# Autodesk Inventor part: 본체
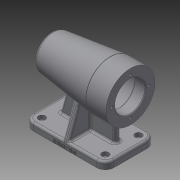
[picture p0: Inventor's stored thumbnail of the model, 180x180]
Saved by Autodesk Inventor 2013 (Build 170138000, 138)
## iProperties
Created: 2018-09
Part Number: 본체
Material: 일반
Document SubType Name: Modeling
Designer: Administrator
Density: 1 g/cm^3
Author: Administrator
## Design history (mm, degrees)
sketch "스케치1"
  geometry: L1 (0, 0)-(0, 34); L2 (0, 34)-(-28, 34); L3 (-28, 34)-(-108.27, 24.144); L4 (-112, 0)-(0, 0); A1 r 80 centre (-32, 0) between (-108.27, 24.144) and (-112, 0); 1 further point
  constraints: 8 end point, 2 point on circle, 1 centre point, 1 coincident, 1 horizontal alignment, 1 perpendicular, 1 vertical
  dimensions: "d0" = 68 diameter of L2 L4; "d3" = 28 distance of L1.end L2.end; "d4" = 7 deg angle of L2 L3; "d5" = 160 diameter of A1; "d6" = 112 distance from line of L1 L4.start
revolve "회전1" sketch "스케치1" stored, may be unused: angle "d7" = 90 deg
hole "구멍1" diameter "d10" = 42; stored, may be unused: countersink angle "d14" = 90 deg, drill point angle "d16" = 0 deg; dims "d11" = 6, "d12" = 4, "d13" = 2, "d15" = 15, "d17" = 10, "d18" = 10
sketch "스케치2"
  geometry: C1 r 21 at (0, 0) reference; C2 r 24 at (0, 0)
  constraints: 1 centre point, 1 coincident
  dimensions: "d19" = 48 diameter of C2
extrude "돌출1" cut sketch "스케치2" distance "d21" = 54; taper "d22" = 0 deg
hole "구멍2" diameter "d25" = 42; stored, may be unused: countersink angle "d29" = 90 deg, drill point angle "d31" = 0 deg; dims "d26" = 6, "d27" = 4, "d28" = 2, "d30" = 12, "d32" = 10, "d33" = 10
hole "구멍3" diameter "d36" = 35; stored, may be unused: countersink angle "d40" = 90 deg, drill point angle "d42" = 0 deg; dims "d37" = 6, "d38" = 4, "d39" = 2, "d41" = 18, "d43" = 10, "d44" = 10
hole "구멍4" diameter "d47" = 32; stored, may be unused: countersink angle "d51" = 90 deg, drill point angle "d53" = 0 deg; dims "d48" = 6, "d49" = 4, "d50" = 2, "d52" = 4, "d54" = 10, "d55" = 10
hole "구멍5" diameter "d58" = 21; stored, may be unused: countersink angle "d62" = 90 deg, drill point angle "d64" = 0 deg; dims "d56" = 10, "d57" = 10, "d59" = 6, "d60" = 4, "d61" = 2, "d63" = 3
fillet "모깎기1" dims "d65" = 3
fillet "모깎기2" dims "d66" = 0.3
chamfer "모따기1" distance "d67" = 1; stored, may be unused: second distance "d68" = 2, angle "d69" = 45 deg
sketch "스케치3"
  geometry: C1 r 34 at (0, 0) reference; 1 further point
  constraints: 1 vertical alignment
  dimensions: "d70" = 26 distance of C1.centre point (0, 26)
hole "구멍6" sketch "스케치3" at (0, 26) diameter "d71" = 3.242; stored, may be unused: countersink angle "d75" = 90 deg, drill point angle "d77" = 118 deg; dims "d72" = 8, "d73" = 4, "d74" = 2, "d76" = 11
node "작업 평면1"
sketch "스케치4"
  geometry: L1 (-112, -35)-(0, -35); L2 (0, -35)-(0, 35); L3 (0, 35)-(-112, 35); L4 (-112, 35)-(-112, -35); 2 further points
  constraints: 8 end point, 2 coincident, 2 parallel, 1 horizontal, 1 midpoint, 1 perpendicular
  dimensions: "d82" = 70 distance of L1.end L2.end; "d84" = 112 distance of L2.end L3.end
extrude "돌출2" join sketch "스케치4" distance "d85" = 10; taper "d86" = 0 deg
fillet "모깎기3" dims "d87" = 12
node "작업 평면2"
node "작업 평면3"
sketch "스케치11"
  geometry: L1 (0, -23)-(0, 23) reference; L2 (-100, 35)-(-12, 35) reference; L3 (-112, -23)-(-112, 23) reference; L4 (0, 23)-(0, -23) reference; L5 (-12, -35)-(-100, -35) reference; L6 (-52, 4)-(-18, 4); L7 (-18, 4)-(-18, -4); L8 (-18, -4)-(-52, -4); L9 (-52, -4)-(-52, 4); A1 r 12 centre (-100, 23) between (-100, 35) and (-112, 23) reference; A2 r 12 centre (-100, -23) between (-112, -23) and (-100, -35) reference; A3 r 12 centre (-12, 23) between (0, 23) and (-12, 35) reference; A4 r 12 centre (-12, -23) between (-12, -35) and (0, -23) reference; 3 further points
  constraints: 8 end point, 2 parallel, 1 horizontal, 1 horizontal alignment, 1 midpoint, 1 perpendicular
  dimensions: "d128" = 18 distance between parallel lines of L1 L7; "d129" = 8 distance of L6.end L7.end
extrude "돌출6" join sketch "스케치11" stored distance "d130" = 8; taper "d131" = 0 deg
sketch "스케치12"
  geometry: A1 r 12 centre (-100, 23) between (-100, 35) and (-112, 23) reference; A2 r 12 centre (-100, -23) between (-112, -23) and (-100, -35) reference; 3 further points
  constraints: 2 coincident
hole "구멍8" sketch "스케치12" at (-100, 23), (-100, -23) diameter "d132" = 5.5; stored, may be unused: countersink angle "d136" = 90 deg, drill point angle "d138" = 118 deg; dims "d133" = 8, "d134" = 9.5, "d135" = 5.4, "d137" = 11
sketch "스케치13"
  geometry: A1 r 12 centre (-12, -23) between (-12, -35) and (0, -23) reference; A2 r 12 centre (-12, 23) between (0, 23) and (-12, 35) reference; 3 further points
  constraints: 2 coincident
hole "구멍9" sketch "스케치13" at (-12, 23), (-12, -23) diameter "d139" = 5.5; stored, may be unused: countersink angle "d143" = 90 deg, drill point angle "d145" = 118 deg; dims "d140" = 8, "d141" = 9.5, "d142" = 5.4, "d144" = 11
sketch "스케치14"
  geometry: L1 (0, 0)-(88, 0) reference; L2 (100, 0)-(100, 10) reference; 3 further points
  constraints: 1 other
  dimensions: "d153" = 3 distance from line of L1 point (44, 3); "d155" = 56 distance from line of L2 point (44, 3)
feature "엠보싱1" sketch "스케치14" dims "d149" = 0.5, "d150" = 0
fillet "모깎기10" dims "d151" = 3
fillet "모깎기11" dims "d152" = 3
fillet "모깎기12" dims "d156" = 3
node "작업 평면4"
sketch "스케치15"
  geometry: L1 (-35, -69.423)-(-35.5, -69.423) reference; L2 (-35.5, -69.423)-(-35.5, -69.092) reference; L3 (-35.5, -69.092)-(-35, -69.092) reference; L4 (-35, -69.092)-(-35, -67) reference; L5 (-32, -64)-(32, -64) reference; L6 (35, -67)-(35, -74) reference; L7 (35, -74)-(-35, -74) reference; L8 (-35, -74)-(-35, -69.423) reference; L9 (-34.819, -65.974)-(-16.98, -16.961); L10 (16.976, -16.951)-(34.819, -65.974); L11 (-35, -69.423)-(-35.5, -69.423) reference; L12 (-35.5, -69.423)-(-35.5, -69.092) reference; L13 (-35.5, -69.092)-(-35, -69.092) reference; L14 (-35, -69.092)-(-35, -67) reference; L15 (-32, -64)-(32, -64) reference; L16 (35, -67)-(35, -74) reference; L17 (35, -74)-(-35, -74) reference; L18 (-35, -74)-(-35, -69.423) reference; L19 (-35, -69.423)-(-35.5, -69.423) reference; L20 (-35.5, -69.423)-(-35.5, -69.092) reference; L21 (-35.5, -69.092)-(-35, -69.092) reference; L22 (-35, -69.092)-(-35, -67) reference; L23 (-32, -64)-(32, -64) reference; L24 (35, -67)-(35, -74) reference; L25 (35, -74)-(-35, -74) reference; L26 (-35, -74)-(-35, -69.423) reference; L27 (-35, -69.423)-(-35.5, -69.423) reference; L28 (-35.5, -69.423)-(-35.5, -69.092) reference; L29 (-35.5, -69.092)-(-35, -69.092) reference; L30 (-35, -69.092)-(-35, -67) reference; L31 (-32, -64)-(32, -64) reference; L32 (35, -67)-(35, -74) reference; L33 (35, -74)-(-35, -74) reference; L34 (-35, -74)-(-35, -69.423) reference; L35 (-35, -69.423)-(-35.5, -69.423) reference; L36 (-35.5, -69.423)-(-35.5, -69.092) reference; L37 (-35.5, -69.092)-(-35, -69.092) reference; L38 (-35, -69.092)-(-35, -67) reference; L39 (-32, -64)-(32, -64) reference; L40 (35, -67)-(35, -74) reference; L41 (35, -74)-(-35, -74) reference; L42 (-35, -74)-(-35, -69.423) reference; L43 (23, -67)-(-23, -67) reference; L44 (-34.819, -65.974)-(34.819, -65.974); C1 r 30.562 at (0, 0) reference; C2 r 30.562 at (0, 0) reference; C3 r 24 at (0, 0) reference; C4 r 24 at (0, 0) reference; C5 r 30.562 at (0, 0) reference; C6 r 24 at (0, 0) reference; C7 r 30.562 at (0, 0) reference; C8 r 24 at (0, 0) reference; C9 r 30.562 at (0, 0) reference; C10 r 24 at (0, 0) reference; A1 r 3 centre (-32, -67) between (-32, -64) and (-35, -67) reference; A2 r 3 centre (32, -67) between (35, -67) and (32, -64) reference; A3 r 3 centre (-32, -67) between (-32, -64) and (-35, -67) reference; A4 r 3 centre (32, -67) between (35, -67) and (32, -64) reference; A5 r 3 centre (-32, -67) between (-32, -64) and (-35, -67) reference; A6 r 3 centre (32, -67) between (35, -67) and (32, -64) reference; A7 r 3 centre (-32, -67) between (-32, -64) and (-35, -67) reference; A8 r 3 centre (32, -67) between (35, -67) and (32, -64) reference; A9 r 3 centre (-32, -67) between (-32, -64) and (-35, -67) reference; A10 r 3 centre (32, -67) between (35, -67) and (32, -64) reference; A11 r 24 centre (0, 0) between (-16.98, -16.961) and (16.98, -16.961); 2 further points
  constraints: 6 end point, 4 point on circle, 2 tangent, 1 centre point, 1 coincident, 1 point on line, 2 other
  dimensions: "d158" = 20 deg angle of L6 L10; "d159" = 20 deg angle of L8 L9
extrude "돌출7" join sketch "스케치15" stored distance "d160" = 8; taper "d161" = 0 deg
sketch "스케치16"
  geometry: L1 (99, -17.2)-(99, -16) reference; L2 (99, -16)-(102.7, -16) reference; L3 (103, -15.7)-(103, -10.5) reference; L4 (106, -7.5)-(106, 7.5) reference; L5 (103, 10.5)-(103, 15.7) reference; L6 (102.7, 16)-(99, 16) reference; L7 (99, 16)-(99, 17.2) reference; L8 (98.7, 17.5)-(81, 17.5) reference; L9 (81, 17.5)-(81, 20.7) reference; L10 (80.7, 21)-(69, 21) reference; L11 (66, 24)-(18, 24) reference; L12 (15, 21)-(1, 21) reference; L13 (1, 21)-(0, 22) reference; L14 (0, 22)-(0, 24.379) reference; L15 (0, 24.379)-(11, 24.379) reference; L16 (11, 24.379)-(11.974, 26) reference; L17 (11.974, 26)-(11, 27.621) reference; L18 (11, 27.621)-(0, 27.621) reference; L19 (0, 27.621)-(0, 34) reference; L20 (0, 34)-(27.817, 34) reference; L21 (28.182, 33.978)-(106.331, 24.382) reference; L22 (106.331, -24.382)-(60, -30.071) reference; L23 (60, -30.071)-(60, -64) reference; L24 (60, -64)-(109, -64) reference; L25 (112, -67)-(112, -74) reference; L26 (112, -74)-(0, -74) reference; L27 (0, -74)-(0, -67) reference; L28 (3, -64)-(18, -64) reference; L29 (18, -64)-(18, -37) reference; L30 (15, -34)-(0, -34) reference; L31 (0, -34)-(0, -27.621) reference; L32 (0, -27.621)-(11, -27.621) reference; L33 (11, -27.621)-(11.974, -26) reference; L34 (11.974, -26)-(11, -24.379) reference; L35 (11, -24.379)-(0, -24.379) reference; L36 (0, -24.379)-(0, -22) reference; L37 (0, -22)-(1, -21) reference; L38 (1, -21)-(15, -21) reference; L39 (18, -24)-(66, -24) reference; L40 (69, -21)-(80.7, -21) reference; L41 (81, -20.7)-(81, -17.5) reference; L42 (81, -17.5)-(98.7, -17.5) reference; L43 (94, -64)-(82.905, -22.595); A1 r 0.3 centre (98.7, -17.2) between (98.7, -17.5) and (99, -17.2) reference; A2 r 0.3 centre (102.7, -15.7) between (102.7, -16) and (103, -15.7) reference; A3 r 3 centre (103, -7.5) between (103, -10.5) and (106, -7.5) reference; A4 r 3 centre (103, 7.5) between (106, 7.5) and (103, 10.5) reference; A5 r 0.3 centre (102.7, 15.7) between (103, 15.7) and (102.7, 16) reference; A6 r 0.3 centre (98.7, 17.2) between (99, 17.2) and (98.7, 17.5) reference; A7 r 0.3 centre (80.7, 20.7) between (81, 20.7) and (80.7, 21) reference; A8 r 3 centre (66, 21) between (69, 21) and (66, 24) reference; A9 r 3 centre (18, 21) between (18, 24) and (15, 21) reference; A10 r 3 centre (27.817, 31) between (28.182, 33.978) and (27.817, 34) reference; A11 r 3 centre (105.965, 21.405) between (108.847, 22.238) and (106.331, 24.382) reference; A12 r 80 centre (32, 0) between (108.847, -22.238) and (108.847, 22.238) reference; A13 r 3 centre (105.965, -21.405) between (106.331, -24.382) and (108.847, -22.238) reference; A14 r 3 centre (109, -67) between (112, -67) and (109, -64) reference; A15 r 3 centre (3, -67) between (3, -64) and (0, -67) reference; A16 r 3 centre (15, -37) between (18, -37) and (15, -34) reference; A17 r 3 centre (18, -21) between (15, -21) and (18, -24) reference; A18 r 3 centre (66, -21) between (66, -24) and (69, -21) reference; A19 r 0.3 centre (80.7, -20.7) between (80.7, -21) and (81, -20.7) reference; 1 further point
  constraints: 2 end point, 1 point on line
  dimensions: "d162" = 18 distance from line of L25 L43.start; "d163" = 105 deg angle of L24 L43
feature "리브3" sketch "스케치16" dims "d164" = 1, "d165" = 8, "d166" = 0, "d167" = 0, "d168" = 1, "d169" = 1
fillet "모깎기13" dims "d170" = 3
fillet "모깎기14" dims "d171" = 3
fillet "모깎기15" dims "d172" = 3
node "솔리드1"
pattern_circular "원형 패턴1" dims angle "d79" = 360 deg
node "절단 모서리 투영5"
node "절단 모서리 투영6"
node "절단 모서리 투영7"
node "절단 모서리 투영8"
node "절단 모서리 투영9"
node "절단 모서리 투영10"
node "절단 모서리 투영11"
other parameters: "d81" = -74, "d96" = -56, "d115" = -56, "d157" = -56
